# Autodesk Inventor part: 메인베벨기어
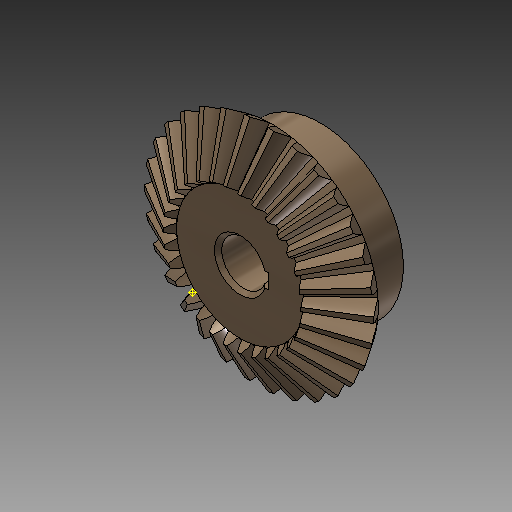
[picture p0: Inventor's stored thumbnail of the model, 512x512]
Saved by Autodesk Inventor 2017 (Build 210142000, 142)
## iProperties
Created: 2018-09
Part Number: 메인베벨기어
Material: 강철, 탄소
Document SubType Name: Modeling
Categories: <?xml version="1.0" encoding="UTF-16"?> <MemberInstance><Categories><FamilyTemplate><FamilyTemplateParameter ValueType="xs:double" Id="1" ObjectReferenceKey="da
Mass: 290.333 g
Surface Area: 107.716 cm^2
Volume: 36.8911 cm^3
Density: 7.87 g/cm^3
Appearance: 얼룩무늬
CustomPartVersion: 1
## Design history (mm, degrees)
node "맨 위 점"
node "메쉬 평면2"
sketch "톱니 본체 스케치"
  geometry: L1 (0, 0)-(28.669, -21.997); L2 (28.669, -21.997)-(31.109, -18.336); L3 (31.109, -18.336)-(0, 0); L4 (30, -20)-(0, 0); L5 (17.219, -13.212)-(18.685, -11.013); L6 (28.669, -21.997)-(17.219, -13.212); L7 (31.109, -18.336)-(18.685, -11.013); L8 (0, -39.387)-(0, 6.564) reference; L9 (0, -20)-(31.109, -20)
  constraints: 16 end point, 4 point on line, 3 perpendicular, 2 collinear, 1 horizontal alignment, 1 vertical alignment
  dimensions: "d0" = 60 diameter of L4.start L8 (= da_de); "d1" = 57.33744 diameter of L1.end L8 (= da_dfe); "d2" = 62.2188 diameter of L2.end L8 (= da_dae); "d3" = 14.4 distance between parallel lines of L2 L5 (= da_b); "d4" = 18.3359 vertical distance of L2.end L1.start (= da_ve)
revolve "톱니 본체" sketch "톱니 본체 스케치" stored, may be unused: angle "d5" = 90 deg
node "시작점"
node "톱니 평면"
sketch "시작 스케치"
  geometry: L1 (0, -23.505)-(0, 10.645) reference; L2 (-0.709, -2.928)-(0.709, -2.928); A1 r 19.188 centre (-19.457, -7.014) between (-0.709, -2.928) and (-3.232, 3.229); A2 r 19.188 centre (19.457, -7.014) between (3.232, 3.229) and (0.709, -2.928); A3 r 57.403 centre (0, -54.083) between (3.232, 3.229) and (-3.232, 3.229); 1 further point
  constraints: 6 point on circle, 3 centre point, 3 symmetric about line, 2 end point, 1 coincident, 1 perpendicular, 1 other
  dimensions: "d7" = 19.18795 radius of A1 (= fd_rr); "d8" = 19.45712 horizontal distance of point (0, -54.083) A1.centre (= fd_x); "d9" = 47.06905 vertical distance of point (0, -54.083) A1.centre (= fd_y); "d57" = 57.40327 radius of A3 (= 0.5 x fd_dva + 0.3 x da_he); "d58" = 51.15527 distance from line of A3.centre L2 (= 0.5 x fd_dva - 1.12 x da_he)
node "끝점"
  node "끝 평면"
sketch "3D 스케치 오른쪽"
  node "Helical Curve Right" dims "d65" = 229.90621 (computed from da_dm, da_delta, da_beta), "d66" = 31.5, "d67" = 60 (= da_de), "d68" = -9.82794 (= -da_delta), "d69" = 8.10972 (computed from fd_loft, da_delta)
node "끝 평면 오른쪽"
sketch "끝 스케치 오른쪽"
  geometry: L1 (0, -41.54)-(0, 13.178) reference; L2 (-0.422, -1.69)-(0.422, -1.69); A1 r 11.427 centre (-11.587, -4.123) between (-0.422, -1.69) and (-1.925, 1.977); A2 r 11.427 centre (11.587, -4.123) between (1.925, 1.977) and (0.422, -1.69); A3 r 34.184 centre (0, -32.153) between (1.925, 1.977) and (-1.925, 1.977); 1 further point
  constraints: 6 point on circle, 3 centre point, 3 symmetric about line, 2 end point, 1 coincident, 1 perpendicular, 1 other
  dimensions: "d70" = 11.58699 horizontal distance of A3.centre A1.centre (computed from fd_x, fd_ratio); "d71" = 28.03028 vertical distance of point (0, -32.153) A1.centre (computed from fd_y, fd_ratio); "d72" = 11.4267 radius of A1 (computed from fd_rr, fd_ratio); "d73" = 30.46369 distance from line of point (0, -32.153) L2 (computed from d58, fd_ratio); "d74" = 34.18446 radius of A3 (computed from d57, fd_ratio)
feature "로프트 오른쪽" sketch "끝 스케치 오른쪽" dims "d75" = 0, "d77" = 0, "d79" = 0, "d80" = 90 deg, "d85" = 20, "d92" = 90 deg, "d93" = 90 deg, "da_teethtype" = 0 [user parameter]
sketch "3D 스케치 왼쪽"
  node "Helical Curve Left" dims "d26" = 229.90621 (computed from da_dm, da_delta, da_beta), "d27" = 8.10972 (computed from fd_loft, da_delta), "d28" = 60 (= da_de), "d29" = -9.82794 (= -da_delta)
node "끝 평면 왼쪽"
sketch "끝 스케치 왼쪽" dims "d56" = 10.3728 (derived)
  geometry: L1 (0, -43.753)-(0, 15.405) reference; L2 (-0.422, -1.678)-(0.422, -1.678); A1 r 11.427 centre (-11.587, -4.111) between (-0.422, -1.678) and (-1.925, 1.988); A2 r 11.427 centre (11.587, -4.111) between (1.925, 1.988) and (0.422, -1.678); A3 r 34.184 centre (0, -32.142) between (1.925, 1.988) and (-1.925, 1.988); 2 further points; 1 other entity
  constraints: 6 point on circle, 3 centre point, 3 symmetric about line, 2 end point, 1 coincident, 2 other
  dimensions: "d30" = 11.4267 radius of A1 (computed from fd_rr, fd_ratio); "d31" = 11.58699 horizontal distance of point (0, -32.142) A1.centre (computed from fd_x, fd_ratio); "d32" = 28.03028 vertical distance of A1.centre point (0, -32.142) (computed from fd_y, fd_ratio); "d61" = 34.18446 radius of A3 (computed from d57, fd_ratio); "d62" = 30.46369 distance from line of point (0, -32.142) L2 (computed from d58, fd_ratio)
feature "로프트 왼쪽" sketch "끝 스케치 왼쪽" dims "d35" = 0, "d37" = 0, "d39" = 0, "d40" = 90 deg, "d84" = 10, "d90" = 90 deg, "d91" = 90 deg, "da_teethtype" = 0 [user parameter]
sketch "본체 스케치"
  geometry: L1 (0, -35.038)-(0, -19.531) reference; L2 (28.669, -21.997)-(17.219, -13.212) reference; L3 (17.219, -13.212)-(0, -13.212); L4 (28.669, -21.997)-(0, -21.997)
  constraints: 4 end point, 2 perpendicular, 2 point on line
revolve "본체 고정" sketch "본체 스케치" stored, may be unused: angle "d46" = 90 deg
feature "피치 지름" dims angle "d47" = 90 deg
sketch "스케치8"
  geometry: C1 r 22.5 at (0, 0); 1 further point
  constraints: 1 centre point, 1 coincident
  dimensions: "d94" = 45 diameter of C1
extrude "돌출1" join sketch "스케치8" distance "d95" = 13; taper "d96" = 0 deg
sketch "스케치9"
  geometry: 1 further point
hole "구멍1" sketch "스케치9" at (0, 0) diameter "d97" = 12; stored, may be unused: countersink angle "d101" = 90 deg, drill point angle "d103" = 118 deg; dims "d98" = 6, "d99" = 4, "d100" = 2, "d102" = 8
sketch "스케치10"
  geometry: L1 (5.657, 2)-(7.8, 2); L2 (7.8, 2)-(7.8, -2); L3 (7.8, -2)-(5.657, -2); A1 r 6 centre (0, 0) between (5.657, 2) and (5.657, -2) reference; 1 further point
  constraints: 6 end point, 2 parallel, 2 point on circle, 1 horizontal, 1 perpendicular
  dimensions: "d104" = 4 distance of L1.end L2.end; "d112" = 13.8 dimension on A1 L2
extrude "돌출2" cut sketch "스케치10" stored distance "d106" = 10; taper "d107" = 0 deg
chamfer "모따기1" distance "d108" = 1; stored, may be unused: second distance "d109" = 2, angle "d110" = 45 deg
fillet "모깎기1" dims "d111" = 2
body "Solid1"
feature "로프트" dims "d17" = 0, "d18" = 90 deg, "d19" = 0, "d20" = 90 deg, "d89" = 0, "da_teethtype" = 0 [user parameter]
pattern_circular "원형 패턴" dims angle "d22" = 360 deg, "d88" = 0, "da_teethtype" = 0 [user parameter]
pattern_circular "원형 패턴 오른쪽" dims angle "d82" = 360 deg, "da_teethtype" = 0 [user parameter]
pattern_circular "원형 패턴 왼쪽" dims angle "d42" = 360 deg, "da_teethtype" = 0 [user parameter]
sketch "끝 스케치"
  geometry: L1 (0, -15.359)-(0, 6.983) reference; L2 (-0.422, -1.69)-(0.422, -1.69); A1 r 11.427 centre (-11.587, -4.123) between (-0.422, -1.69) and (-1.925, 1.977); A2 r 11.427 centre (11.587, -4.123) between (1.925, 1.977) and (0.422, -1.69); A3 r 34.184 centre (0, -32.153) between (1.925, 1.977) and (-1.925, 1.977); 1 further point
  constraints: 6 point on circle, 3 centre point, 3 symmetric about line, 2 end point, 1 coincident, 1 other
  dimensions: "d12" = 11.4267 radius of A1 (computed from fd_rr, fd_ratio); "d15" = 11.58699 horizontal distance of A1.centre point (0, -32.153) (computed from fd_x, fd_ratio); "d16" = 28.03028 vertical distance of A1.centre point (0, -32.153) (computed from fd_y, fd_ratio); "d59" = 34.18446 radius of A3 (computed from d57, fd_ratio); "d60" = 30.46369 distance from line of A3.centre L2 (computed from d58, fd_ratio)
sketch "Sketch6"
  geometry: L1 (30, -20)-(0, 0) reference; L2 (0, -37.8)-(0, 6.3) reference
body "Srf1"
other parameters: "da_b" = 14.4 [user parameter; used in 2 equation terms], "da_de" = 60 [user parameter; used in 4 equation terms], "da_dae" = 62.2188 [user parameter; used in 2 equation terms], "da_dfe" = 57.33744 [user parameter; used in 1 equation term], "da_le" = 36.05551 [user parameter; used in 1 equation term], "da_omega" = 90 deg [user parameter; used in 1 equation term], "da_beta" = 0 [user parameter; used in 2 equation terms], "da_delta" = 9.82794 [user parameter; used in 8 equation terms], "da_alpha" = 20 deg [user parameter; used in 2 equation terms], "da_he" = 4.4 [user parameter; used in 4 equation terms], "da_ve" = 18.3359 [user parameter; used in 1 equation term], "fd_dv" = 108.16654 (computed from da_de, da_delta) [user parameter; used in 1 equation term], "fd_dva" = 112.16654 (computed from da_dae, da_delta) [user parameter; used in 3 equation terms], "fd_dvb" = 101.6433 (computed from fd_dv, da_alpha) [user parameter; used in 2 equation terms], "da_zv" = 540.83269 [user parameter; used in 1 equation term], "fd_loft" = 14.62 (= da_b + 0.05 x da_he) [user parameter; used in 4 equation terms], "fd_ratio" = 5.95514 (computed from da_le, fd_loft) [user parameter; used in 15 equation terms], "fd_rr" = 19.18795 (computed from fd_dd, fd_dvb) [user parameter; used in 6 equation terms], "fd_angle" = 0.29367 (computed from da_zv) [user parameter; used in 4 equation terms], "fd_x1" = 1.58802 (computed from da_dvw, fd_angle) [user parameter; used in 1 equation term], "fd_y1" = 54.05995 (computed from da_dvw, fd_angle) [user parameter; used in 1 equation term], "fd_x2" = 17.8691 (computed from fd_rr, fd_angle2, fd_angle) [user parameter; used in 1 equation term], "fd_y2" = 6.9909 (computed from fd_rr, fd_angle2, fd_angle) [user parameter; used in 1 equation term], "fd_x" = 19.45712 (= fd_x1 + fd_x2) [user parameter; used in 4 equation terms], "fd_y" = 47.06905 (= fd_y1 - fd_y2) [user parameter; used in 4 equation terms], "fd_angle2" = 3.43555 (computed from fd_dvb, fd_dd, da_alpha) [user parameter; used in 2 equation terms], "fd_dd" = 108.64654 (= fd_dva - 0.8 x da_he) [user parameter; used in 2 equation terms], "da_dvw" = 108.16654 [user parameter; used in 2 equation terms], "d11" = 14.62 (= fd_loft), "da_dm" = 48.01848 [user parameter; used in 2 equation terms], "da_x" = 0 [user parameter], "da_m" = 2 [user parameter], "d48" = 0, "d49" = 0, "d50" = 90 deg (= da_omega), "d51" = 6 deg (computed from da_z), "d52" = 0, "d53" = 0, "d54" = 0
